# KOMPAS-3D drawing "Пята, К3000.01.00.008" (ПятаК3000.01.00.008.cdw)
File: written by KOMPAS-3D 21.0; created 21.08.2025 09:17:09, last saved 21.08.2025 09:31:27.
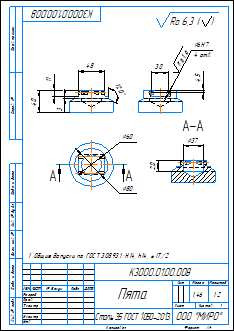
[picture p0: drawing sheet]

Sheet 1: A4, portrait

Document properties: Автор: admin; Полное имя файла: C:\Users\ShavarinML\Desktop\Стапель\2D\ПятаК3000.01.00.008.cdw; Знак неуказанной шероховатости: 4; Параметр неуказанной шероховатости: Ra 6,3; Масса: 1.463

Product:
- Part/product: Пята  | designation К3000.01.00.008
    Материал: Сталь 35 ГОСТ 1050-2013 (density 7826 kg/m3)
    Масса: 1.463
  - Body: Тело 1
      Масса: 1.045653

Title block, sheet 1: Наименование: Пята; designation: К3000.01.00.008; Материал: Сталь 35 ГОСТ 1050-2013; Масса: 1,46; Количество листов документа: 1; organisation: ООО "МИРО"; Форматы листов документа: A4

Views: Спереди 1, Спереди, Проекционный вид 2, Проекционный вид 3, Разрез А-А
Referenced files in C:\Users\ShavarinML\Desktop\Стапель\от тм\Стрела 2\: Пята 7007-0046 ГОСТ 13437-68.m3d
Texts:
  Ra 1,6
  Ra 6,3
  Ra 6,3 ( )
  К3000.01.00.008 Пята
Dimensions and other numbers on the sheet: 48; 40; 11; 3; 120; 0; 80; 60; 4,5; 30; 6; 4 отв.; 37; 20; 1:2; 1; 1,46

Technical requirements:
  Общие допуски по ГОСТ 30893.1: H14, h14,   IT/2.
